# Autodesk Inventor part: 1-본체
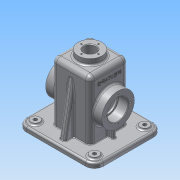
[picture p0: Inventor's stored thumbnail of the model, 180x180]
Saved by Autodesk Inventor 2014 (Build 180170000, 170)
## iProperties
Created: 2015-12
Part Number: 1-본체
Material: 알루미늄 6061
Document SubType Name: Modeling
Designer: Administrator
Density: 2.71 g/cm^3
Appearance: 알루미늄 - 평지
Mass: 860.643 g
Surface Area: 908.789 cm^2
Volume: 317.581 cm^3
Author: Administrator
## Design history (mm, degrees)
sketch "스케치1"
  geometry: L1 (-50, 52.5)-(50, 52.5); L2 (60, 42.5)-(60, -42.5); L3 (50, -52.5)-(-50, -52.5); L4 (-60, -42.5)-(-60, 42.5); A1 r 10 centre (-50, 42.5) between (-50, 52.5) and (-60, 42.5); A2 r 10 centre (50, 42.5) between (60, 42.5) and (50, 52.5); A3 r 10 centre (50, -42.5) between (50, -52.5) and (60, -42.5); A4 r 10 centre (-50, -42.5) between (-60, -42.5) and (-50, -52.5); 6 further points
  constraints: 8 end point, 8 point on circle, 8 tangent, 6 point on line, 4 centre point, 3 equal radius, 2 midpoint, 2 parallel, 1 horizontal, 1 horizontal alignment, 1 perpendicular, 1 vertical alignment
  dimensions: "d0" = 120 distance of point (-60, 52.5) point (60, 52.5); "d1" = 105 distance of point (60, 52.5) point (60, -52.5); "d2" = 10 radius of A1
extrude "돌출1" new body sketch "스케치1" distance "d3" = 2; taper "d4" = 0 deg
sketch "스케치2"
  geometry: L1 (-50, 57.5)-(50, 57.5); L2 (65, 42.5)-(65, -42.5); L3 (50, -57.5)-(-50, -57.5); L4 (-65, -42.5)-(-65, 42.5); A1 r 15 centre (-50, 42.5) between (-50, 57.5) and (-65, 42.5); A2 r 15 centre (50, 42.5) between (65, 42.5) and (50, 57.5); A3 r 15 centre (50, -42.5) between (50, -57.5) and (65, -42.5); A4 r 15 centre (-50, -42.5) between (-65, -42.5) and (-50, -57.5); 6 further points
  constraints: 8 end point, 8 point on circle, 8 tangent, 6 point on line, 4 centre point, 3 equal radius, 2 midpoint, 2 parallel, 1 horizontal, 1 horizontal alignment, 1 perpendicular, 1 vertical alignment
  dimensions: "d5" = 115 distance of point (65, 57.5) point (65, -57.5); "d6" = 130 distance of point (-65, 57.5) point (65, 57.5); "d7" = 15 radius of A1
extrude "돌출2" join sketch "스케치2" distance "d8" = 8; taper "d9" = 0 deg
sketch "스케치3"
  geometry: C1 r 7.5 at (-50, 42.5); C2 r 7.5 at (50, 42.5); C3 r 7.5 at (-50, -42.5); C4 r 7.5 at (50, -42.5); C5 r 3 at (-50, 42.5); C6 r 3 at (50, 42.5); C7 r 3 at (50, -42.5); C8 r 3 at (-50, -42.5); A1 r 15 centre (-50, 42.5) between (-50, 57.5) and (-65, 42.5) reference; A2 r 15 centre (-50, -42.5) between (-65, -42.5) and (-50, -57.5) reference; A3 r 15 centre (50, -42.5) between (50, -57.5) and (65, -42.5) reference; A4 r 15 centre (50, 42.5) between (65, 42.5) and (50, 57.5) reference; 1 further point
  constraints: 8 centre point, 8 coincident, 6 equal radius
  dimensions: "d10" = 15 diameter of C1; "d13" = 6 diameter of C5
extrude "돌출3" join sketch "스케치3" distance "d11" = 3; taper "d12" = 0 deg
extrude "돌출4" cut sketch "스케치3" stored distance "d14" = 3; taper "d15" = 0 deg
sketch "스케치4"
  geometry: L1 (-32.5, 110)-(32.5, 110); L2 (32.5, 110)-(32.5, 0); L3 (32.5, 0)-(-32.5, 0); L4 (-32.5, 0)-(-32.5, 110); 2 further points
  constraints: 8 end point, 2 coincident, 2 parallel, 1 horizontal, 1 midpoint, 1 perpendicular
  dimensions: "d16" = 110 distance between parallel lines of L3 L1; "d17" = 65 distance of L1.start L1.end
extrude "돌출5" join sketch "스케치4" stored distance "d18" = 65; taper "d19" = 0 deg
sketch "스케치5"
  geometry: C1 r 20 at (32.5, 32.5); 1 further point
  constraints: 1 centre point, 1 coincident
  dimensions: "d20" = 40 diameter of C1
extrude "돌출6" join sketch "스케치5" distance "d21" = 10; taper "d22" = 0 deg
fillet "모깎기1" dims "d23" = 8
sketch "스케치6"
  geometry: L1 (-52.5, 2)-(-57.5, 2) reference; L2 (-57.5, 2)-(-57.5, 10) reference; L3 (-57.5, 10)-(-32.5, 10) reference; L4 (-32.5, 10)-(-32.5, 102) reference; L5 (-24.5, 110)-(-20, 110) reference; L6 (-20, 110)-(-20, 120) reference; L7 (-20, 120)-(20, 120) reference; L8 (20, 120)-(20, 110) reference; L9 (20, 110)-(24.5, 110) reference; L10 (32.5, 102)-(32.5, 10) reference; L11 (32.5, 10)-(57.5, 10) reference; L12 (57.5, 10)-(57.5, 2) reference; L13 (57.5, 2)-(52.5, 2) reference; L14 (52.5, 2)-(52.5, 0) reference; L15 (52.5, 0)-(-52.5, 0) reference; L16 (-52.5, 0)-(-52.5, 2) reference; L17 (-32.5, 95.069)-(-47.5, 10); L18 (32.5, 95.069)-(47.5, 10); C1 r 27.5 at (0, 55); A1 r 8 centre (-24.5, 102) between (-24.5, 110) and (-32.5, 102) reference; A2 r 8 centre (24.5, 102) between (32.5, 102) and (24.5, 110) reference; 2 further points
  constraints: 4 end point, 4 point on line, 1 centre point, 1 equal length, 1 midpoint, 1 vertical alignment
  dimensions: "d24" = 55 distance from line of L15 C1.centre; "d25" = 55 diameter of C1; "d28" = 10 distance from line of L17.end L2; "d29" = 10 deg angle of L17 L2; "d30" = 10 deg angle of L18 L12
  node "절단 모서리 투영1"
extrude "돌출7" join sketch "스케치6" stored distance "d26" = 95; taper "d27" = 0 deg
extrude "돌출8" join sketch "스케치6" stored distance "d31" = 10; taper "d32" = 0 deg
sketch "스케치7"
  geometry: L1 (-27.5, 105)-(27.5, 105); L2 (27.5, 105)-(27.5, 0); L3 (27.5, 0)-(-27.5, 0); L4 (-27.5, 0)-(-27.5, 105); L5 (-32.5, 67.49)-(-32.5, 102) reference; L6 (-24.5, 110)-(24.5, 110) reference; L7 (-60, 2)-(-65, 2) reference; L8 (-65, 2)-(-65, 10) reference; L9 (-65, 10)-(-32.5, 10) reference; L10 (-32.5, 10)-(-32.5, 27.5) reference; L11 (-32.5, 27.5)-(-47.5, 27.5) reference; L12 (-47.5, 27.5)-(-47.5, 82.5) reference; L13 (-47.5, 82.5)-(-32.5, 82.5) reference; L14 (-32.5, 82.5)-(-32.5, 102) reference; L15 (-24.5, 110)-(-20, 110) reference; L16 (-20, 110)-(-20, 120) reference; L17 (-20, 120)-(20, 120) reference; L18 (20, 120)-(20, 110) reference; L19 (20, 110)-(24.5, 110) reference; L20 (32.5, 102)-(32.5, 82.5) reference; L21 (32.5, 82.5)-(47.5, 82.5) reference; L22 (47.5, 82.5)-(47.5, 27.5) reference; L23 (47.5, 27.5)-(32.5, 27.5) reference; L24 (32.5, 27.5)-(32.5, 10) reference; L25 (32.5, 10)-(65, 10) reference; L26 (65, 10)-(65, 2) reference; L27 (65, 2)-(60, 2) reference; L28 (60, 2)-(60, 0) reference; L29 (60, 0)-(-60, 0) reference; L30 (-60, 0)-(-60, 2) reference; L31 (42.5, 36.604)-(42.5, 10); L32 (42.5, 10)-(32.5, 10); L33 (32.5, 10)-(32.5, 36.604); L34 (32.5, 36.604)-(42.5, 36.604); L35 (-42.5, 36.604)-(-32.5, 36.604); L36 (-32.5, 36.604)-(-32.5, 10); L37 (-32.5, 10)-(-42.5, 10); L38 (-42.5, 10)-(-42.5, 36.604); A1 r 8 centre (-24.5, 102) between (-24.5, 110) and (-32.5, 102) reference; A2 r 8 centre (24.5, 102) between (32.5, 102) and (24.5, 110) reference; 10 further points
  constraints: 24 end point, 9 midpoint, 6 parallel, 3 perpendicular, 2 equal length, 2 horizontal, 2 horizontal alignment, 2 vertical alignment, 1 coincident
  dimensions: "d33" = 5 distance between parallel lines of L5 L4; "d34" = 5 distance between parallel lines of L6 L1; "d38" = 15 distance between parallel lines of L2 L31; "d39" = 26.60359 distance between parallel lines of L32 L34
  node "절단 모서리 투영2"
extrude "돌출9" cut sketch "스케치7" stored distance "d35" = 55; taper "d36" = 0 deg
extrude "돌출10" join sketch "스케치7" stored distance "d40" = 6; taper "d41" = 0 deg
hole "구멍1" diameter "d44" = 20; stored, may be unused: countersink angle "d48" = 90 deg, drill point angle "d50" = 118 deg; dims "d42" = 10, "d43" = 10, "d45" = 6, "d46" = 4, "d47" = 2, "d49" = 8
sketch "스케치8"
  geometry: C1 r 10 at (0, 0) reference; 1 further point
  constraints: 1 vertical alignment
  dimensions: "d51" = 14.5 distance of point (0, 14.5) C1.centre
hole "구멍2" sketch "스케치8" at (0, 14.5) diameter "d52" = 2.459; stored, may be unused: countersink angle "d56" = 90 deg, drill point angle "d58" = 118 deg; dims "d53" = 7, "d54" = 4, "d55" = 2, "d57" = 9
sketch "스케치9"
  geometry: C1 r 27.5 at (0, 0) reference; 2 further points
  constraints: 1 vertical alignment
  dimensions: "d62" = 21 distance of C1.centre point (0, 21)
hole "구멍3" sketch "스케치9" at (0, 21) diameter "d63" = 3.242; stored, may be unused: countersink angle "d67" = 90 deg, drill point angle "d69" = 118 deg; dims "d64" = 8, "d65" = 4, "d66" = 2, "d68" = 10
hole "구멍4" diameter "d75" = 30; stored, may be unused: countersink angle "d79" = 90 deg, drill point angle "d81" = 0 deg; dims "d73" = 10, "d74" = 10, "d76" = 8, "d77" = 35, "d78" = 17, "d80" = 10
chamfer "모따기1" distance "d82" = 1; stored, may be unused: second distance "d83" = 2, angle "d84" = 45 deg
sketch "스케치10"
  geometry: L1 (-120, 20)-(-120, -20) reference; A1 r 27.5 centre (-55, 0) between (-67.49, 24.5) and (-67.49, -24.5) reference; 2 further points
  constraints: 1 horizontal alignment, 1 other
  dimensions: "d85" = 26 distance from line of point (-94, 0) L1
feature "엠보싱1" sketch "스케치10" dims "d0" = 120, "d1" = 105, "d2" = 10, "d5" = 115, "d6" = 130, "d7" = 15, "d86" = 0.5, "d87" = 0
fillet "모깎기2" dims "d88" = 0.3, "d89" = 3
fillet "모깎기3" dims "d90" = 3
fillet "모깎기4" dims "d91" = 3
fillet "모깎기5" dims "d92" = 1
node "솔리드1"
pattern_circular "원형 패턴1" dims angle "d60" = 360 deg
pattern_circular "원형 패턴2" dims angle "d71" = 360 deg
mirror "대칭1"
